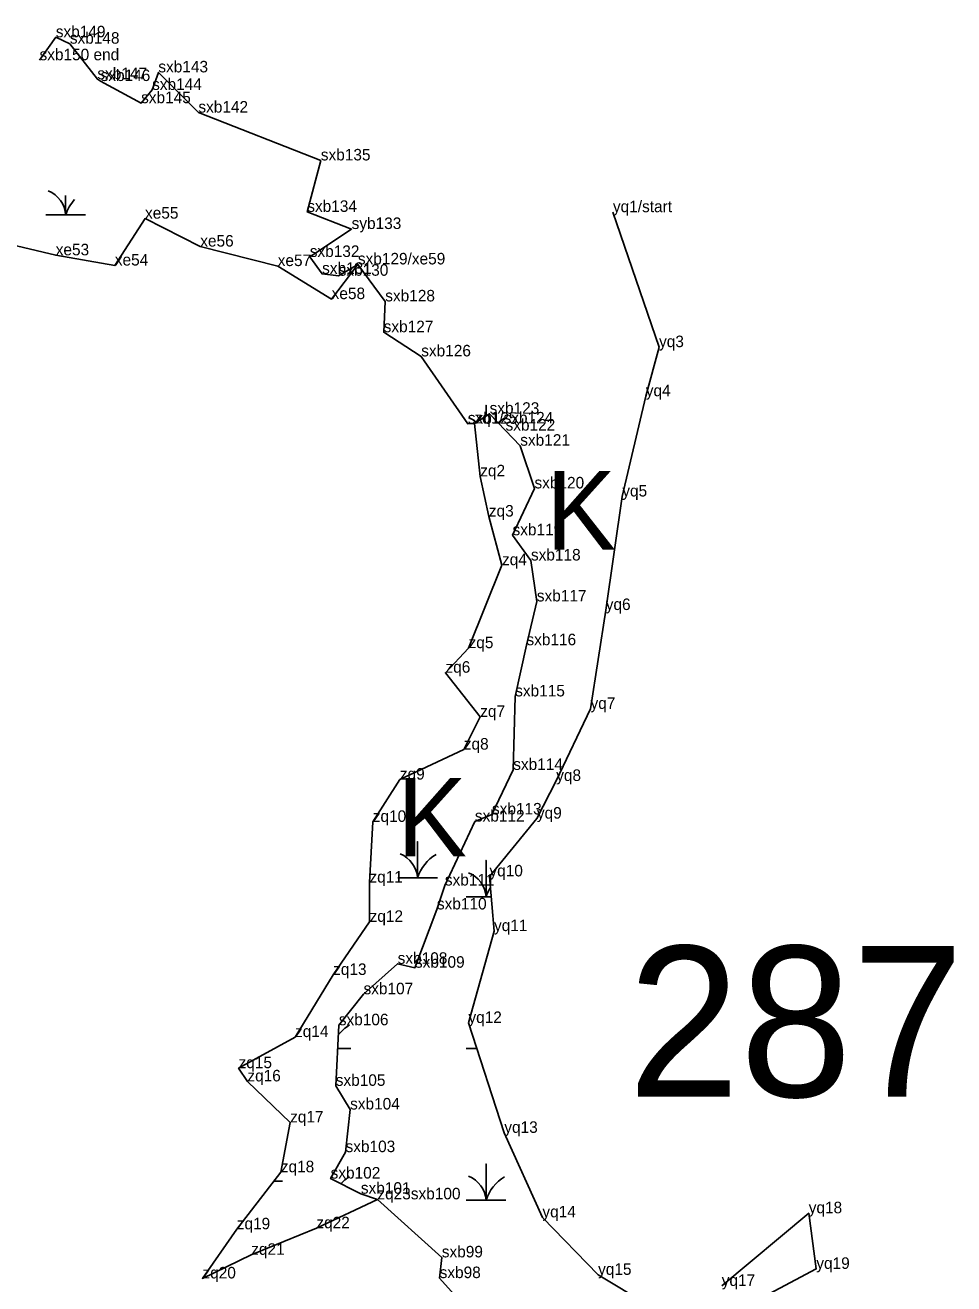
# Model space of a CAD drawing. Extents: x 2072529 to 2268796, y 436423 to 470406.
# Drawn here: x 2246734 to 2247137, y 439982 to 440528 of the extents above; entities that cross this region are included whole.
import ezdxf

# ---------------------------------------------------------------- set-up
doc = ezdxf.new("R2010")
doc.units = 0
for name, color, linetype in [('Default', 7, 'Continuous'), ('Exist Environmental Wetland Boundary Cogo Comment', 7, 'Continuous'), ('Exist Environmental Wetland Boundary Cogo Point CELL', 7, 'Continuous'), ('Exist Hydro Jurisdictional Stream or Body of Water NEU Mitigable Cogo Comment', 7, 'Continuous'), ('Old_Level_20', 7, 'Continuous'), ('Old_Level_52', 7, 'Continuous')]:
    doc.layers.add(name, color=color, linetype=linetype)

msp = doc.modelspace()

# ---------------------------------------------------------------- linework, layer by layer
at = {"layer": 'Exist Environmental Wetland Boundary Cogo Point CELL'}
for points in [[(2246742.86, 440445.77), (2246751.46, 440445.77), (2246751.46, 440454.19)], [(2246751.46, 440454.19), (2246751.46, 440445.77), (2246760.07, 440445.77)], [(2246933.82, 440358.54), (2246933.82, 440363.21), (2246933.82, 440358.54)], [(2246895.52, 440158.24), (2246904.12, 440158.24), (2246904.12, 440174.02), (2246904.12, 440158.24), (2246912.73, 440158.24)], [(2246925.22, 440150.03), (2246933.82, 440150.03), (2246933.82, 440165.81), (2246933.82, 440150.03), (2246936.04, 440150.03)], [(2246869.45, 440084.23), (2246875.17, 440084.23)], [(2246925.22, 440084.23), (2246929.8, 440084.23)], [(2246925.22, 440018.43), (2246933.82, 440018.43), (2246933.82, 440034.21), (2246933.82, 440018.43), (2246942.42, 440018.43)], [(2246866.57, 440027.77), (2246866.57, 440028.14)], [(2246866.57, 440028.14), (2246866.57, 440027.77)], [(2246841.77, 440026.64), (2246845.48, 440026.64)]]:
    msp.add_lwpolyline(points, dxfattribs=at)
for centre, radius, start, end in [((2246739.2, 440444.89), 12.3, 4.1403, 67.535), ((2246769.71, 440439.71), 19.22, 138.5208, 161.6222), ((2246921.55, 440346.54), 12.3, 49.1703, 67.535), ((2246952.06, 440341.37), 19.22, 122.1274, 132.3184), ((2246891.86, 440157.35), 12.3, 4.1403, 67.535), ((2246922.37, 440152.18), 19.22, 122.1274, 161.6222), ((2246921.55, 440149.14), 12.3, 4.1403, 67.535), ((2246952.06, 440143.97), 19.22, 148.3307, 161.6222), ((2246884.81, 440078.17), 19.22, 122.1274, 141.5956), ((2246921.55, 440083.34), 12.3, 66.8067, 67.535), ((2246884.81, 440012.37), 19.22, 122.1274, 136.4709), ((2246921.55, 440017.54), 12.3, 4.1403, 67.535), ((2246952.06, 440012.37), 19.22, 122.1274, 161.6222)]:
    msp.add_arc(centre, radius, start, end, dxfattribs=at)
at = {"layer": 'Old_Level_20'}
for p, q in [((2246747.18, 440522.81), (2246747.18, 440522.81)), ((2246753.27, 440520.05), (2246753.27, 440520.05)), ((2246740.13, 440512.87), (2246740.13, 440512.87)), ((2246791.67, 440507.6), (2246791.67, 440507.6)), ((2246765.22, 440504.65), (2246765.22, 440504.65)), ((2246766.63, 440503.85), (2246766.63, 440503.85)), ((2246788.96, 440499.99), (2246788.96, 440499.99)), ((2246784.19, 440494.25), (2246784.19, 440494.25)), ((2246809.04, 440490.17), (2246809.04, 440490.17)), ((2246862.15, 440469.41), (2246862.15, 440469.41)), ((2246785.9, 440444.17), (2246785.9, 440444.17)), ((2246856.28, 440447.1), (2246856.28, 440447.1)), ((2246988.87, 440446.97), (2246988.87, 440446.97)), ((2246875.52, 440439.67), (2246875.52, 440439.67)), ((2246809.85, 440432.05), (2246809.85, 440432.05)), ((2246747.16, 440428.26), (2246747.16, 440428.26)), ((2246857.35, 440427.54), (2246857.35, 440427.54)), ((2246772.8, 440423.83), (2246772.8, 440423.83)), ((2246843.46, 440423.6), (2246843.46, 440423.6)), ((2246862.71, 440420.23), (2246862.71, 440420.23)), ((2246878.23, 440424.32), (2246878.23, 440424.32)), ((2246878.23, 440424.32), (2246878.23, 440424.32)), ((2246869.89, 440419.4), (2246869.89, 440419.4)), ((2246866.86, 440409.26), (2246866.86, 440409.26)), ((2246890.11, 440408.27), (2246890.11, 440408.27)), ((2246889.43, 440394.91), (2246889.43, 440394.91)), ((2247008.88, 440388.43), (2247008.88, 440388.43)), ((2246905.71, 440384.42), (2246905.71, 440384.42)), ((2247003.12, 440367.13), (2247003.12, 440367.13)), ((2246925.93, 440355.21), (2246925.93, 440355.21)), ((2246928.79, 440355.34), (2246928.79, 440355.34)), ((2246928.79, 440355.34), (2246928.79, 440355.34)), ((2246935.37, 440359.53), (2246935.37, 440359.53)), ((2246942.3, 440352.25), (2246942.3, 440352.25)), ((2246948.67, 440345.68), (2246948.67, 440345.68)), ((2246931.31, 440332.4), (2246931.31, 440332.4)), ((2246954.83, 440327.16), (2246954.83, 440327.16)), ((2246992.93, 440323.66), (2246992.93, 440323.66)), ((2246935.05, 440314.95), (2246935.05, 440314.95)), ((2246945.31, 440306.83), (2246945.31, 440306.83)), ((2246953.31, 440295.9), (2246953.31, 440295.9)), ((2246940.75, 440293.86), (2246940.75, 440293.86)), ((2246955.86, 440278.13), (2246955.86, 440278.13)), ((2246985.76, 440274.42), (2246985.76, 440274.42)), ((2246926.26, 440257.88), (2246926.26, 440257.88)), ((2246951.35, 440259.15), (2246951.35, 440259.15)), ((2246916.23, 440247.23), (2246916.23, 440247.23)), ((2246946.47, 440236.95), (2246946.47, 440236.95)), ((2246979.14, 440231.52), (2246979.14, 440231.52)), ((2246931.31, 440228.04), (2246931.31, 440228.04)), ((2246924.18, 440213.88), (2246924.18, 440213.88)), ((2246945.62, 440205.06), (2246945.62, 440205.06)), ((2246896.44, 440200.88), (2246896.44, 440200.88)), ((2246964.27, 440200.27), (2246964.27, 440200.27)), ((2246936.41, 440185.75), (2246936.41, 440185.75)), ((2246884.69, 440182.53), (2246884.69, 440182.53)), ((2246929, 440182.68), (2246929, 440182.68)), ((2246955.89, 440183.95), (2246955.89, 440183.95)), ((2246935.3, 440158.89), (2246935.3, 440158.89)), ((2246883.24, 440156.21), (2246883.24, 440156.21)), ((2246915.96, 440154.93), (2246915.96, 440154.93)), ((2246912.52, 440144.56), (2246912.52, 440144.56)), ((2246883.32, 440139.17), (2246883.32, 440139.17)), ((2246937.29, 440135.16), (2246937.29, 440135.16)), ((2246895.49, 440120.97), (2246895.49, 440120.97)), ((2246867.49, 440116.15), (2246867.49, 440116.15)), ((2246902.99, 440119.28), (2246902.99, 440119.28)), ((2246880.67, 440107.77), (2246880.67, 440107.77)), ((2246869.96, 440094.33), (2246869.96, 440094.33)), ((2246926.18, 440095.31), (2246926.18, 440095.31)), ((2246850.97, 440089.2), (2246850.97, 440089.2)), ((2246826.48, 440075.71), (2246826.48, 440075.71)), ((2246830.3, 440069.98), (2246830.3, 440069.98)), ((2246868.63, 440068.05), (2246868.63, 440068.05)), ((2246874.85, 440057.79), (2246874.85, 440057.79)), ((2246848.82, 440052.16), (2246848.82, 440052.16)), ((2246941.76, 440047.66), (2246941.76, 440047.66)), ((2246872.88, 440039.29), (2246872.88, 440039.29)), ((2246844.8, 440030.56), (2246844.8, 440030.56)), ((2246866.41, 440027.85), (2246866.41, 440027.85)), ((2246879.52, 440021.27), (2246879.52, 440021.27)), ((2246886.69, 440018.82), (2246886.69, 440018.82)), ((2246886.69, 440018.82), (2246886.69, 440018.82)), ((2246958.27, 440011), (2246958.27, 440011)), ((2247073.81, 440012.79), (2247073.81, 440012.79)), ((2246825.7, 440005.83), (2246825.7, 440005.83)), ((2246860.23, 440006.28), (2246860.23, 440006.28)), ((2246831.96, 439994.76), (2246831.96, 439994.76)), ((2246914.63, 439993.65), (2246914.63, 439993.65)), ((2246810.8, 439984.52), (2246810.8, 439984.52)), ((2246913.7, 439984.66), (2246913.7, 439984.66)), ((2246982.43, 439986.07), (2246982.43, 439986.07)), ((2247077.1, 439988.66), (2247077.1, 439988.66))]:
    msp.add_line(p, q, dxfattribs=at)
for points in [[(2246713.51, 440436.32), (2246747.16, 440428.26), (2246772.8, 440423.83), (2246785.9, 440444.17), (2246809.85, 440432.05), (2246843.46, 440423.6), (2246866.86, 440409.26), (2246878.23, 440424.32)], [(2246988.87, 440446.97), (2247008.88, 440388.43), (2247003.12, 440367.13), (2246992.93, 440323.66), (2246985.76, 440274.42), (2246979.14, 440231.52), (2246964.27, 440200.27), (2246955.89, 440183.95), (2246935.3, 440158.89), (2246937.29, 440135.16), (2246926.18, 440095.31), (2246941.76, 440047.66), (2246958.27, 440011), (2246982.43, 439986.07), (2247003.93, 439973.25)], [(2246928.79, 440355.34), (2246931.31, 440332.4), (2246935.05, 440314.95), (2246940.75, 440293.86), (2246926.26, 440257.88), (2246916.23, 440247.23), (2246931.31, 440228.04), (2246924.18, 440213.88), (2246896.44, 440200.88), (2246884.69, 440182.53), (2246883.24, 440156.21), (2246883.32, 440139.17), (2246867.49, 440116.15), (2246850.97, 440089.2), (2246826.48, 440075.71), (2246830.3, 440069.98), (2246848.82, 440052.16), (2246844.8, 440030.56), (2246825.7, 440005.83), (2246810.8, 439984.52), (2246831.96, 439994.76), (2246860.23, 440006.28), (2246886.69, 440018.82)], [(2247036.07, 439981.26), (2247073.81, 440012.79), (2247077.1, 439988.66), (2247052.26, 439975.5)]]:
    msp.add_lwpolyline(points, dxfattribs=at)
at = {"layer": 'Old_Level_52'}
for points in [[(2246740.13, 440512.87), (2246747.18, 440522.81), (2246753.27, 440520.05), (2246765.22, 440504.65), (2246766.63, 440503.85), (2246784.19, 440494.25), (2246788.96, 440499.99), (2246791.67, 440507.6), (2246809.04, 440490.17), (2246862.15, 440469.41), (2246856.28, 440447.1), (2246875.52, 440439.67), (2246857.35, 440427.54)], [(2246857.35, 440427.54), (2246862.71, 440420.23), (2246869.89, 440419.4), (2246878.23, 440424.32), (2246890.11, 440408.27), (2246889.43, 440394.91), (2246905.71, 440384.42), (2246925.93, 440355.21), (2246928.79, 440355.34), (2246935.37, 440359.53), (2246942.3, 440352.25), (2246948.67, 440345.68), (2246954.83, 440327.16), (2246945.31, 440306.83), (2246953.31, 440295.9), (2246955.86, 440278.13), (2246951.35, 440259.15), (2246946.47, 440236.95), (2246945.62, 440205.06), (2246936.41, 440185.75), (2246929, 440182.68), (2246915.96, 440154.93), (2246912.52, 440144.56), (2246902.99, 440119.28), (2246895.49, 440120.97), (2246880.67, 440107.77), (2246869.96, 440094.33), (2246868.63, 440068.05), (2246874.85, 440057.79), (2246872.88, 440039.29), (2246866.41, 440027.85), (2246879.52, 440021.27), (2246886.69, 440018.82), (2246914.63, 439993.65), (2246913.7, 439984.66), (2246921.26, 439976.09)]]:
    msp.add_lwpolyline(points, dxfattribs=at)

# ---------------------------------------------------------------- texts
at = {"layer": 'Default'}
msp.add_text('287', height=65.34, dxfattribs=at).set_placement((2246995.37, 440063.3))
at = {"layer": 'Exist Environmental Wetland Boundary Cogo Comment'}
for s, p in [('xe55', (2246785.9, 440444.17)), ('yq1/start', (2246988.87, 440446.97)), ('xe56', (2246809.85, 440432.05)), ('xe53', (2246747.16, 440428.26)), ('xe54', (2246772.8, 440423.83)), ('yq3', (2247008.88, 440388.43)), ('yq4', (2247003.12, 440367.13)), ('zq2', (2246931.31, 440332.4)), ('yq5', (2246992.93, 440323.66)), ('zq3', (2246935.05, 440314.95)), ('zq4', (2246940.75, 440293.86)), ('yq6', (2246985.76, 440274.42)), ('zq5', (2246926.26, 440257.88)), ('zq6', (2246916.23, 440247.23)), ('yq7', (2246979.14, 440231.52)), ('zq7', (2246931.31, 440228.04)), ('zq8', (2246924.18, 440213.88)), ('zq9', (2246896.44, 440200.88)), ('yq8', (2246964.27, 440200.27)), ('zq10', (2246884.69, 440182.53)), ('yq9', (2246955.89, 440183.95)), ('yq10', (2246935.3, 440158.89)), ('zq11', (2246883.24, 440156.21)), ('zq12', (2246883.32, 440139.17)), ('yq11', (2246937.29, 440135.16)), ('zq13', (2246867.49, 440116.15)), ('yq12', (2246926.18, 440095.31)), ('zq14', (2246850.97, 440089.2)), ('zq15', (2246826.48, 440075.71)), ('zq16', (2246830.3, 440069.98)), ('zq17', (2246848.82, 440052.16)), ('yq13', (2246941.76, 440047.66)), ('zq18', (2246844.8, 440030.56)), ('yq18', (2247073.81, 440012.79)), ('zq19', (2246825.7, 440005.83)), ('zq22', (2246860.23, 440006.28)), ('yq14', (2246958.27, 440011)), ('zq21', (2246831.96, 439994.76)), ('zq20', (2246810.8, 439984.52)), ('yq15', (2246982.43, 439986.07)), ('yq19', (2247077.1, 439988.66)), ('yq17', (2247036.07, 439981.26))]:
    msp.add_text(s, height=5, dxfattribs=at).set_placement(p)
at = {"layer": 'Exist Environmental Wetland Boundary Cogo Point CELL'}
for p in [(2246959.86, 440300.66), (2246895.2, 440167.58)]:
    msp.add_text('K', height=34, dxfattribs=at).set_placement(p)
at = {"layer": 'Exist Hydro Jurisdictional Stream or Body of Water NEU Mitigable Cogo Comment'}
for s, p in [('sxb149', (2246747.18, 440522.81)), ('sxb148', (2246753.27, 440520.05)), ('sxb150 end', (2246740.13, 440512.87)), ('sxb147', (2246765.22, 440504.65)), ('sxb146', (2246766.63, 440503.85)), ('sxb143', (2246791.67, 440507.6)), ('sxb144', (2246788.96, 440499.99)), ('sxb145', (2246784.19, 440494.25)), ('sxb142', (2246809.04, 440490.17)), ('sxb135', (2246862.15, 440469.41)), ('sxb134', (2246856.28, 440447.1)), ('syb133', (2246875.52, 440439.67)), ('sxb132', (2246857.35, 440427.54)), ('xe57', (2246843.46, 440423.6)), ('sxb129/xe59', (2246878.23, 440424.32)), ('sxb131', (2246862.71, 440420.23)), ('sxb130', (2246869.89, 440419.4)), ('xe58', (2246866.86, 440409.26)), ('sxb128', (2246890.11, 440408.27)), ('sxb127', (2246889.43, 440394.91)), ('sxb126', (2246905.71, 440384.42)), ('sxb125', (2246925.93, 440355.21)), ('zq1/sxb124', (2246928.79, 440355.34)), ('sxb123', (2246935.37, 440359.53)), ('sxb122', (2246942.3, 440352.25)), ('sxb121', (2246948.67, 440345.68)), ('sxb120', (2246954.83, 440327.16)), ('sxb119', (2246945.31, 440306.83)), ('sxb118', (2246953.31, 440295.9)), ('sxb117', (2246955.86, 440278.13)), ('sxb116', (2246951.35, 440259.15)), ('sxb115', (2246946.47, 440236.95)), ('sxb114', (2246945.62, 440205.06)), ('sxb113', (2246936.41, 440185.75)), ('sxb112', (2246929, 440182.68)), ('sxb111', (2246915.96, 440154.93)), ('sxb110', (2246912.52, 440144.56)), ('sxb108', (2246895.49, 440120.97)), ('sxb109', (2246902.99, 440119.28)), ('sxb107', (2246880.67, 440107.77)), ('sxb106', (2246869.96, 440094.33)), ('sxb105', (2246868.63, 440068.05)), ('sxb104', (2246874.85, 440057.79)), ('sxb103', (2246872.88, 440039.29)), ('sxb102', (2246866.41, 440027.85)), ('sxb101', (2246879.52, 440021.27)), ('zq23sxb100', (2246886.69, 440018.82)), ('sxb99', (2246914.63, 439993.65)), ('sxb98', (2246913.7, 439984.66))]:
    msp.add_text(s, height=5, dxfattribs=at).set_placement(p)

doc.saveas('drawing.dxf')
